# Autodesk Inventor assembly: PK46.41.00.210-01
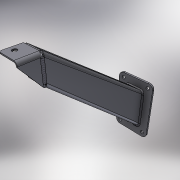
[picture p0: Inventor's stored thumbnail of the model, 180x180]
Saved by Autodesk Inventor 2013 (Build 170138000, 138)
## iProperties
Created: 2012-02
Part Number: PK46.41.00.210-01
Document SubType Name: Weldment
Designer: tedescj
Weld Material: Welded Aluminum-6061
Author: tedescj
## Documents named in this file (5)
- C:\Product Design Suite 2013 Test Drive\Dynamic Simulation\Workspace\Assy, Chassis, Front\PK46.41.00.210-01.iam
- C:\Product Design Suite 2013 Test Drive\Dynamic Simulation\Workspace\Assy, Chassis, Front\PK46.41.00.011.ipt
- C:\Product Design Suite 2013 Test Drive\Dynamic Simulation\Workspace\Assy, Chassis, Front\PK46.41.00.012-01.ipt
- C:\Product Design Suite 2013 Test Drive\Dynamic Simulation\Workspace\Assy, Chassis, Front\PK46.41.00.011-01.ipt
- C:\Product Design Suite 2013 Test Drive\Dynamic Simulation\Workspace\Assy, Chassis, Front\PK46.41.00.013.ipt
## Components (4 placed, 4 different names)
1. PK46.41.00.011:1
2. PK46.41.00.012-01:1
3. PK46.41.00.011-01:1
4. PK46.41.00.013:1
